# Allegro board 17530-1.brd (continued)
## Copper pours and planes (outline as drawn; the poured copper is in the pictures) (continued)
3D3V_S0 on L3SGND: 181.31,140.4 177.1,144.6 177.1,149.65 175.83,152.19 175.83,152.22 175.81,152.24 175.45,153.58 175.18,155.61 174.69,155.95 172.25,164.31 168.59,167.97 168.59,169.62 167.85,170.37 159.85,170.37 157.36,172.88 157,173.22 156.83,173.52 156.69,174.43 157.26,175 157.26,175.47 156.6,176.13 156.6,179.81 152.54,183.97 152.39,184.13 152.39,184.43 152.4,184.48 152.39,184.5 152.39,184.8 152.4,184.84 152.39,184.88 152.39,185.55 152.51,185.69 152.76,185.69 154.48,185.69 155.42,185.69 156.36,185.69 159.29,182.6 159.2,176.48 159.3,176.21 159.69,175.83 170.1,175.83 174.17,171.77 180.64,171.77 181.17,171.24 181.17,170.5 181.16,170.49 181.17,170.42 181.17,164.89 181.93,164.13 181.93,159.56 183.58,157.91 183.58,146.99 184.33,146.24 192.96,146.24 193.74,145.46 193.74,141.3 192.95,140.4 182.15,140.4 182.12,140.41 182.08,140.4 181.79,140.4 181.78,140.41 181.72,140.4
3D3V_S0 on L3SGND: 111.84,173.04 108.92,175.96 95.93,175.96 95.91,175.93 74.37,175.96 73.36,176.97 70.56,176.97 61.67,185.86 59.01,185.86 58.81,186.06 56.45,188.54 56.45,188.55 56.4,188.6 56.34,188.66 56.34,188.66 56.26,188.66 56.19,188.66 56.19,188.66 36.02,188.66 35.37,189.31 35.37,190.55 37.67,192.85 39.67,192.85 40.82,191.71 58.34,191.71 60.88,189.17 64.07,189.17 65.8,187.93 71.15,184.37 73.31,183.1 73.99,182.69 77.14,182.69 77.41,182.42 77.41,180.01 78.15,179.26 110.16,179.26 113.21,176.21 118.19,176.21 118.7,176.72 119.56,176.72 120.21,176.07 120.21,173.4 120.02,173.04
3D3V_S5 on TOP: 160.4,157.99 155.83,162.56 155.83,164.59 152.91,167.51 152.91,173.23 151,175.13 146.53,175.13 143.79,177.88 115.07,177.88 115.06,177.88 114.55,177.88 114.05,178.38 110.26,178.38 110.08,178.56 103.38,178.56 103.12,178.31 103.12,176.91 103,176.78 101.47,176.78 100.97,177.29 88.77,177.29 88.39,177.67 88.39,180.04 88.77,180.42 114.3,180.42 114.9,179.82 143.9,179.82 147.45,176.28 152.02,176.28 154.18,174.12 154.18,168.02 157.3,164.9 157.3,163.32 159.97,160.66 161.8,160.66 162.18,160.27 162.18,158.24 161.93,157.99
3D3V_S5 on TOP: 184.35,43.48 184.15,43.69 184.15,44.2 185.62,45.67 186.51,45.67 188.09,47.24 188.09,136.78 186.56,138.3 186.56,138.35 186.06,138.86 186.06,145.92 186.94,146.81 188.72,146.81 189.48,146.05 189.48,145.14 187.48,143.13 187.48,139.24 189.56,137.16 189.56,46.51 186.54,43.48
3D3V_S5 on TOP: 29.41,178.13 29.4,178.14 28.77,178.14 28.47,178.44 28.47,189.74 28.63,189.89 29.77,189.89 29.95,189.71 29.95,188.14 30.07,188.01 35.29,188.01 35.49,187.81 35.49,183.32 33.43,181.25 33.43,178.66 32.89,178.13
3D3V_S5 on TOP: 35.94,233.3 35.69,233.55 35.69,235.48 35.86,235.66 36.53,235.66 36.68,235.81 36.68,236.52 36.8,236.65 37.31,236.65 37.34,236.63 37.87,236.63 38.23,236.98 38.23,240.54 37.85,240.92 37.85,243.08 37.62,243.31 36.96,243.31 36.75,243.51 36.75,246.15 36.93,246.33 38.79,246.33 41.53,243.59 41.53,236.22 40.01,234.7 40.01,233.43 39.88,233.3 ; 5 cut-outs
3D3V_S5 on TOP: 176.83,4.19 176.78,4.24 176.78,5.21 176.45,5.54 176.45,6.73 176.5,6.78 177.16,6.78 177.65,7.26 177.65,8.1 178.18,8.64 178.92,8.64 179.04,8.51 179.04,6.73 178.89,6.58 178.05,6.58 177.67,6.2 177.67,4.29 177.57,4.19 ; 1 cut-out
3D3V_S5 on TOP: 11.94,186.82 8.76,189.99 4.32,189.99 1.27,193.04 1.27,232.28 13.53,244.54 17.6,244.54 18.38,245.31 23.8,245.31 24.05,245.06 24.05,242.6 23.65,242.19 14.73,242.19 3.94,231.39 3.94,222.76 4.19,222.5 5.59,222.5 6.17,221.92 6.17,221.17 6.36,220.98 6.36,220.13 6.26,220.03 4.38,220.03 3.39,219.04 3.39,195.23 5.46,193.17 12.29,193.17 15.61,189.85 20.59,189.85 21.08,189.36 21.08,187.07 20.83,186.82 ; 2 cut-outs
3D3V_S5 on BOTTOM: 177.04,32 176.78,32.26 176.78,32.64 176.85,32.7 176.85,33.59 178.05,34.8 178.05,38.63 183.24,43.81 183.64,43.81 184.72,44.89 186.12,44.89 186.46,44.55 186.46,44.37 186.66,44.17 180.05,37.55 180.05,37.1 180.09,37.06 180.09,35.95 179.26,35.13 179.26,33.46 177.8,32
3D3V_S5 on BOTTOM: 50.93,237.87 45.85,242.95 22.17,242.95 21.77,243.36 21.77,245.06 22.07,245.36 47.88,245.36 53.47,239.78 53.47,238 53.34,237.87
3D3V_S5 on L2VCC: 69.55,177.74 59.26,187.9 48.44,187.9 45.26,184.72 37.26,184.72 35.1,182.56 16.73,182.56 16.32,183.07 16.32,188.81 16.14,188.97 16.25,189.44 16.45,189.55 39.45,189.57 41.66,191.76 41.86,191.96 59.36,191.96 69.01,182.31 96.02,182.31 96.29,181.77 95.44,180.93 95.44,178.77 94.41,177.74
3D3V_S5 on L2VCC: 188.01,143.7 187.52,144 187.52,155.78 186.13,157.16 172.51,157.16 171.88,156.53 168.35,156.53 167.72,157.16 159.59,157.16 159.19,157.56 159.19,161.85 159.59,162.24 164.01,162.24 167.18,159.07 187.75,159.07 189.93,156.89 189.93,144.1 189.53,143.7
3D3V_SB on TOP: 151.61,128.12 151.49,128.24 151.49,129.26 151.59,129.36 152.81,129.36 153.42,129.97 153.8,129.97 153.92,129.84 153.92,128.8 153.24,128.12
3D3V_SB on TOP: 171.81,47.7 171.35,48.16 171.35,59.79 171.02,60.12 171.02,66.34 167.97,69.39 167.97,97.59 164.49,101.07 163.12,101.07 160.55,103.63 159.54,103.63 159.28,103.89 159.28,104.65 159.61,104.98 160.81,104.98 163.8,101.98 164.21,101.98 164.24,102.01 165,102.01 169.66,97.35 169.66,70.83 172.67,67.82 172.67,59.98 172.9,59.75 172.9,48.01 172.59,47.7 ; 4 cut-outs
3D3V_SB on TOP: 4.22,211.99 3.68,212.52 3.68,218.16 4.1,218.58 6.21,218.58 6.22,218.57 6.22,216.03 6.99,215.26 8.26,215.26 8.51,215.01 8.51,212.01 8.48,211.99 ; 2 cut-outs
3D3V_SB on TOP: 157.51,144.02 157.25,144.27 157.25,148.11 157.02,148.34 156.46,148.34 156.21,148.59 156.21,149.1 156.46,149.35 157.56,149.35 157.61,149.4 157.61,153.67 158.37,154.43 160.66,154.43 160.67,154.42 160.95,154.42 161.04,154.33 161.04,153.67 160.78,153.42 159.99,153.42 159.99,152.6 159.61,152.22 159.44,152.22 159.33,152.12 159.33,150.42 159.64,150.11 162.23,150.11 162.56,150.44 162.56,150.88 163.42,150.88 163.42,150.7 164.34,150.7 164.64,150.39 164.64,148.89 164.52,148.77 163.75,148.77 163.58,148.95 163.58,149.61 163.45,149.73 162.56,149.73 162.31,149.48 162.31,148.08 162.43,147.96 164.59,147.96 165.1,147.45 165.1,146.69 164.93,146.52 158.99,146.52 158.62,146.15 158.62,144.53 158.12,144.02 ; 23 cut-outs
3D3V_SB on TOP: 156.62,12.62 156.03,13.21 156.03,23.22 155.63,23.62 155.63,24.43 156.01,24.82 156.9,24.82 156.9,24.74 157.23,24.41 157.23,24.33 157.28,24.28 157.28,21.82 157.4,21.69 157.4,14.63 158.27,13.77 159.92,13.77 160.05,13.64 160.05,12.7 159.97,12.62 ; 5 cut-outs
3D3V_SB on TOP: 174.24,46.35 173.99,46.61 173.99,49.91 174.12,50.04 176.28,50.04 176.53,49.78 176.53,46.61 176.28,46.35 ; 1 cut-out
3D3V_SB on TOP: 154.08,139.42 153.95,139.55 153.95,139.93 153.85,140.03 153.31,140.03 153.06,140.28 153.06,141 153.26,141.2 155.35,141.2 155.73,140.82 155.73,140.18 154.97,139.42 ; 1 cut-out
3D3V_SB on TOP: 170.79,34.4 170.5,34.7 168.94,34.7 168.73,34.9 168.73,36.14 169.24,36.65 171.68,36.65 171.86,36.47 171.86,34.7 171.56,34.4
3D3V_SB on TOP: 160.86,155.7 160.78,155.78 160.78,156.34 162.51,158.06 162.51,161.44 162.13,161.82 159.97,161.82 157.96,163.83 157.96,165.51 154.94,168.53 154.94,174.56 154.31,175.2 154.31,177.16 155.07,177.93 160.3,177.93 160.68,177.55 160.68,174.85 160.63,174.8 159.46,174.8 159.31,174.96 159.31,176.28 159.08,176.5 156.57,176.5 156.46,176.4 156.46,174.62 156.59,174.5 156.59,170.31 158.5,168.4 159.51,168.4 159.64,168.28 159.64,166.62 161.42,164.85 162.05,164.85 162.18,164.72 162.18,163.58 162.24,163.51 162.31,163.51 162.31,163.02 162.76,162.56 163.86,162.56 164.67,161.75 165.74,161.75 165.86,161.62 165.86,160.78 165.61,160.53 164.47,160.53 164.08,160.15 164.08,157.1 162.69,155.7 ; 6 cut-outs
3D3V_SB on TOP: 138.38,16.8 138.3,16.88 138.3,18.03 138.3,18.03 138.43,18.16 140.97,18.16 141.1,18.03 141.1,16.93 140.97,16.8 ; 1 cut-out
3D3V_SB on BOTTOM: 154.94,140.08 154.43,140.59 154.43,141.6 155.96,143.13 155.96,146.3 156.34,146.69 156.34,148.34 156.72,148.72 158.37,148.72 158.75,148.34 158.75,143.26 155.57,140.08
3D3V_SB on BOTTOM: 159.56,153.26 159.38,153.44 159.38,154.69 161.67,156.97 162.05,156.97 162.56,156.46 162.56,155.57 160.99,154 160.99,153.72 160.53,153.26
3D3V_SB on BOTTOM: 152.88,128.04 152.02,128.91 152.02,131.44 152.78,132.21 152.78,132.97 151.89,133.86 151.89,139.57 152.53,140.21 152.53,140.59 152.78,140.84 153.67,140.84 154.05,140.46 154.05,132.36 154.46,131.95 154.46,130.48 154.1,130.12 154.1,129.01 154.48,128.63 154.48,128.32 154.2,128.04
3D3V_SB on BOTTOM: outline of 91 points within 6.1,171.81 45.72,239.51
3D3V_SB on BOTTOM: 155.45,23.62 155.19,23.88 155.19,24.77 155.57,25.15 163.19,25.15 165.35,27.3 168.91,27.3 171.83,30.23 171.83,32.51 170.56,33.78 170.56,34.8 170.81,35.05 171.83,35.05 173.35,33.53 173.35,29.46 169.67,25.78 166.37,25.78 164.21,23.62
3D3V_SB on BOTTOM: 148.97,11.56 142.75,17.78 141.48,17.78 141.1,17.4 139.32,17.4 139.19,17.53 139.19,18.8 139.57,19.18 143.51,19.18 149.61,13.08 150.62,13.08 154.94,17.4 154.94,20.07 155.96,21.08 157.1,21.08 157.35,20.83 157.35,19.43 156.46,18.54 156.46,16.64 151.38,11.56
3D3V_SB on L2VCC: 46.21,170.45 45.96,170.69 45.96,171.29 46.31,171.64 49.48,171.64 49.86,172.02 65.23,172.02 66.37,173.16 71.96,173.16 74.37,175.58 96.17,175.55 97.85,177.26 98.36,177.86 98.36,180.39 103.1,185.18 119.56,185.23 120.19,184.59 126.19,184.59 126.7,185.1 150.22,185.1 151.67,184.74 151.69,184.72 151.74,184.72 151.8,184.71 151.82,184.72 160.58,184.72 161.05,184.25 160.72,183.69 160.72,181.16 160.5,180.84 157.16,180.84 157.16,182.2 156.54,182.82 108.76,182.82 104.71,178.77 104.71,174.45 104.44,174.18 78.15,174.18 75.23,171.26 66.98,171.26 66.16,170.45 62.46,170.45 62.41,170.46 62.38,170.45
3D3V_SB on L2VCC: 171.91,46.67 171.51,47.07 171.51,48.82 175.97,53.28 176.74,53.28 178.54,55.13 179.93,55.13 180.72,54.34 184.69,54.34 187.46,57.25 187.52,57.3 187.52,57.3 187.52,57.38 187.52,127.08 186.51,128.08 184.99,128.08 184.34,128.73 184.34,131.49 184.61,131.76 187.25,131.76 189.17,129.84 189.17,50.88 186.61,48.32 181.28,48.32 180.52,47.56 177.47,47.56 176.58,46.67
3D3V_SB on L2VCC: 156.92,114.62 156.65,114.89 156.65,117.68 155.2,119.14 151.25,119.14 150.8,118.68 148.31,118.68 148.15,118.93 148.15,122.45 148.39,122.62 149.78,122.62 149.92,122.48 149.92,122.13 148.91,121.11 148.91,119.8 149.18,119.44 150.04,119.44 150.12,119.52 150.73,120.11 150.83,120.21 156.42,120.21 157.3,121.09 157.66,121.09 157.92,120.83 157.92,115.01 157.53,114.62
3D3V_SB on L3SGND: 30.23,170.45 28.53,172.15 21.8,172.15 15.43,178.51 15.43,179.19 16.32,180.14 16.32,188.67 9.86,195.14 7.06,195.14 5.78,196.42 5.78,196.6 5.9,215.56 6.17,215.84 8.3,215.84 8.7,215.44 8.7,199.31 9.45,198.56 10.72,198.56 18.99,190.29 18.99,178.48 19.48,177.99 21.13,177.99 23.29,175.83 26.59,175.83 27.61,174.82 30.02,174.82 31.67,173.16 48.21,173.16 49.35,172.02 65.23,172.02 66.37,173.16 71.96,173.16 74.37,175.58 96.03,175.55 96.3,175.28 96.3,174.4 96.09,174.18 78.15,174.18 75.23,171.26 66.98,171.26 66.16,170.45
3D3V_SB on L3SGND: 185.12,173.29 184.85,173.56 184.85,179.4 184.36,179.9 168.58,179.9 167.96,179.28 167.96,176.35 167.82,176.21 159.84,176.21 159.58,176.48 159.68,182.75 156.52,186.07 155.42,186.07 154.48,186.07 152.76,186.07 152.34,186.07 152.01,185.7 152.01,184.96 151.7,184.82 151.55,184.97 151.09,185.45 151.08,186.2 151.08,187.23 151.08,187.64 151.44,187.99 154.58,187.99 155.59,188 158.64,186.78 163.5,181.93 185.98,181.93 186.88,181.02 186.88,173.69 186.48,173.29
3D3V_SB on L3SGND: 184.61,128.84 184.34,129.11 184.34,133.56 175.2,142.7 175.2,144.84 174.69,145.6 174.69,149.31 170.76,153.1 166.78,153.1 165.64,154.24 161.34,154.24 160.7,153.61 159.84,153.61 159.58,153.88 159.58,154.35 161.75,156.53 165.66,156.53 166.55,155.64 171.88,155.64 174.36,153.16 174.4,153.11 174.41,153.11 175.48,152.03 176.72,149.56 176.72,144.45 181.69,139.48 181.69,139.46 181.71,139.45 181.72,139.43 181.76,139.41 186.5,134.67 186.5,129.36 185.98,128.84
3D3V_WLAN_SB on TOP: 44.58,208.91 44.32,209.17 41.76,209.17 41.2,209.73 41.2,210.67 41.3,210.77 48.64,210.77 50.04,209.37 50.04,208.91 ; 6 cut-outs
3D3V_WLAN_SB on TOP: 47.88,225.63 47.6,225.91 47.6,226.82 47.04,227.38 41.1,227.38 41.02,227.46 41.02,229.49 40.39,230.12 38.23,230.12 37.47,230.89 37.47,232.79 37.59,232.92 41.27,232.92 41.53,232.66 41.53,231.78 41.67,231.64 50.58,231.64 51.18,231.04 51.18,226.14 50.67,225.63 ; 12 cut-outs
3D3V_WLAN_SB on L2VCC: 47.83,208.98 47.43,209.37 47.43,219 48.96,220.52 48.96,226.39 48.21,227.14 44.91,227.14 44.39,227.66 44.39,229.28 44.73,229.63 44.79,229.68 44.79,229.69 45.04,229.93 51.61,229.93 52.64,228.9 52.64,228.01 52.63,227.98 52.64,227.93 52.64,209.63 51.99,208.98
EDP_AVC12 on TOP: 60.12,18.72 59.59,19.25 57.96,19.25 57.96,19.56 57.99,19.58 59.66,19.58 59.94,19.86 60.83,19.86 61.24,20.27 62.1,20.27 62.18,20.19 62.18,19.74 61.93,19.48 61.37,19.48 60.6,18.72
LAN_CONN_CVT on TOP: 122.1,16.56 121.98,16.68 121.98,18.03 122.12,18.17 123.41,18.17 123.55,18.03 123.55,16.66 123.44,16.56 ; 1 cut-out
PWR_1D0V on TOP: 188.7,146.84 187.91,147.62 187.91,152.63 187.32,153.21 187.32,156.57 187.71,156.95 193.4,156.95 194.44,155.91 194.44,148.59 192.68,146.84 ; 2 cut-outs
PWR_1D0V on BOTTOM: 188.24,146.79 187.83,147.19 187.83,154.76 187.73,154.86 187.73,157.15 187.91,157.33 188.9,157.33 190.4,155.83 193.52,155.83 193.68,155.68 193.68,147.93 192.56,146.81 192.56,146.79
PWR_1D0V_PHASE on TOP: 183.62,160.78 182.98,161.42 182.98,162.53 183.13,162.69 185.29,162.69 185.98,163.37 185.98,167.08 185.55,167.51 185.55,172.59 185.67,172.72 188.47,172.72 188.54,172.64 188.54,167.31 188.81,167.04 190.33,167.04 190.58,166.8 190.58,165.99 190.91,165.66 192.81,165.66 193.68,164.8 193.68,161.67 192.79,160.78 ; 2 cut-outs
PWR_1D0V_PHASE on BOTTOM: 188.59,161.42 186.31,163.7 186.31,170.76 187.86,172.31 188.62,172.31 188.85,172.09 188.85,167.26 189.23,166.88 191.95,166.88 193.29,165.53 193.29,161.8 192.91,161.42
PWR_2D5V on TOP: 113.39,172.34 113.17,172.55 113.17,173.98 113.03,174.12 111.38,174.12 111.28,174.22 111.28,176.2 111.39,176.31 112.83,176.31 113.47,175.67 116.99,175.67 117.6,175.06 117.6,172.42 117.53,172.34 ; 4 cut-outs
PWR_2D5V_VIN on TOP: 108.18,172.11 108.05,172.24 108.05,175.26 107.87,175.44 105.71,175.44 104.98,174.7 103.4,174.7 103.33,174.78 103.33,177.8 103.71,178.18 109.88,178.18 110.9,177.16 110.9,172.19 110.82,172.11
PWR_3D3V on TOP: 22.1,177.29 21.97,177.42 21.97,178.18 22.48,178.69 22.48,181.23 21.84,181.86 21.84,191.11 22.1,191.36 25.7,191.36 26.92,190.14 27.93,190.14 28.16,189.92 28.16,178.18 27.94,177.97 27.94,177.93 27.3,177.29 ; 1 cut-out
PWR_3D3V on BOTTOM: 23.5,178.32 22.62,179.2 22.61,179.2 22.43,179.37 22.43,180.7 21.49,181.64 21.49,190.65 22.35,191.52 26.8,191.52 28.19,190.12 28.19,178.51 28,178.32
PWR_3V_PHASE2 on TOP: 27.48,190.58 27.18,190.88 27.18,191.62 26.77,192.02 18.62,192.02 15.44,195.2 15.44,197.71 16.94,199.21 22.33,199.21 22.86,199.75 22.86,201.04 22.99,201.17 28.83,201.17 28.88,201.12 28.88,198.73 29.08,198.53 32.74,198.53 32.97,198.3 32.97,197.79 32.98,197.78 32.98,192.91 32.83,192.76 28.85,192.76 28.75,192.66 28.75,190.68 28.65,190.58
PWR_3V_PHASE2 on BOTTOM: 18.16,192.66 15.2,195.62 15.2,197.83 15.37,197.99 18.69,197.99 19.08,197.61 32.38,197.61 33.15,196.85 33.15,193.29 32.51,192.66
PWR_5V on TOP: 11.58,222.48 10.54,223.52 10.54,225.81 10.5,225.84 10.5,229.1 11.09,229.68 12.26,229.68 13.56,230.99 33.05,230.99 33.27,230.76 33.27,228.98 32.13,227.84 27.3,227.84 26.92,227.46 26.92,222.61 26.8,222.48 ; 2 cut-outs
PWR_5V on BOTTOM: 11.58,222.83 10.41,224 10.41,224.28 10.43,224.29 10.43,226.71 12.06,228.35 12.06,230.2 12.38,230.52 25.9,230.52 26.42,231.04 32.38,231.04 32.4,231.03 33.13,231.03 33.27,230.89 33.27,228.8 32.23,227.76 32.23,227.71 32.18,227.66 31.47,227.66 29.46,225.65 26.64,225.65 26.09,225.09 22.48,225.09 21.49,224.1 15.47,224.1 14.2,222.83
PWR_5V3D3V_VIN on TOP: 43.81,198.25 42.53,199.53 36.58,199.53 34.81,201.29 34.8,201.29 34.67,201.42 22.86,201.42 22.49,201.79 22.49,213.5 22.77,213.78 29.97,213.78 30.23,213.53 30.23,207.77 30.76,207.24 41.4,207.24 41.41,207.23 42.37,207.24 46.28,205.28 46.55,205.02 46.55,198.44 46.35,198.25
PWR_5V3D3V_VIN on BOTTOM: 38.71,200.28 38.71,204.55 39.01,204.85 46.41,204.85 46.43,204.83 46.43,199.85 46.42,199.83 46.42,199.07 46.1,198.75 40.23,198.75
PWR_5V3D3V_VIN on L2VCC: 23.95,199.71 22.42,201.25 22.42,213.15 23.07,213.8 29.77,213.8 30.16,213.41 30.16,208.33 31.16,207.33 43.26,207.33 46.29,205.75 46.29,200.1 45.9,199.71
PWR_5V_PHASE1 on TOP: 20.32,209.55 19.81,210.06 18.41,210.06 17.78,210.69 17.78,211.96 17.4,212.34 15.37,212.34 14.61,213.11 14.61,220.5 16.18,222.07 27.71,222.07 27.79,222 27.79,216.51 27.56,216.28 24.26,216.28 23.62,215.65 23.62,214.12 23.5,214 22.73,214 22.23,213.49 22.23,209.68 22.1,209.55
PWR_5V_PHASE1 on BOTTOM: 18.03,209.55 17.53,210.06 17.53,211.71 17.14,212.09 15.62,212.09 15,212.71 15,220.71 16.41,222.12 27.56,222.12 27.81,221.87 27.81,217.47 27.28,216.94 22.63,216.94 21.72,216.03 21.72,210.06 21.21,209.55
PWR_12V_DUAL_1D0V on TOP: 189,167.36 188.85,167.51 188.85,173.13 188.37,173.61 187.53,173.61 187.29,173.85 187.29,175.4 187.4,175.51 191.77,175.51 192.02,175.77 192.02,177.04 192.15,177.16 192.79,177.16 192.91,177.04 192.91,176.28 193.29,175.9 193.29,174.24 193.42,174.12 193.42,168.4 193.17,168.15 191.77,168.15 191.64,168.28 191.64,168.76 191.57,168.83 189.89,168.83 189.84,168.78 189.84,167.44 189.76,167.36
PWR_DDR4_LDOIN on TOP: 40.34,181.46 39.52,182.27 39.52,186.08 39.75,186.31 41.02,186.31 41.27,186.06 41.27,181.66 41.07,181.46
PWR_DDR4_LX on TOP: 54.84,173.51 54.7,173.65 54.7,179.13 55.04,179.48 58.04,179.48 58.24,179.68 58.24,181.89 57.56,182.58 57.56,185.9 57.81,186.16 60.83,186.16 60.96,186.03 60.96,184.15 61.47,183.64 63.25,183.64 66.93,179.96 66.93,177.29 66.17,176.54 63.82,176.54 60.79,173.51 ; 1 cut-out
PWR_DDR4_LX on BOTTOM: 55.37,173.99 54.99,174.37 54.99,179.32 55.12,179.45 57.91,179.45 58.17,179.71 58.17,181.36 58.67,181.86 64.64,181.86 67.18,179.32 67.18,177.16 66.67,176.66 63.5,176.66 62.23,175.39 60.96,175.39 59.56,173.99
PWR_GT_SW1 on TOP: 18.01,77.22 17.7,77.52 17.7,80.72 17.4,81.03 15.42,81.03 14.94,81.51 14.94,82.37 14.76,82.55 13.18,82.55 12.78,82.96 12.78,87.07 12.85,87.15 14.61,87.15 14.86,87.4 14.86,90.37 14.73,90.5 13.87,90.5 13.77,90.6 13.77,91.16 14.05,91.44 19.81,91.44 20.32,90.93 20.32,84.84 21.34,83.82 23.5,83.82 23.75,83.57 23.75,77.34 23.62,77.22 ; 1 cut-out
PWR_GT_SW1 on BOTTOM: 15.37,83.95 14.86,84.45 14.86,91.19 15.11,91.44 19.18,91.44 19.68,90.93 19.68,84.33 19.3,83.95
PWR_GT_SW1 on L2VCC: 17.81,77.25 17.67,77.4 17.67,80.62 17.25,81.04 15.4,81.04 15.02,81.41 15.02,82.43 14.58,82.87 12.93,82.87 12.76,83.02 12.76,86.86 12.94,87 12.95,87.01 14.43,87.01 14.9,87.47 14.9,90.15 14.58,90.46 14.02,90.46 13.88,90.6 13.88,91.16 14.18,91.45 19.94,91.45 20.31,91.08 20.31,84.87 20.46,84.68 21.38,83.76 23.44,83.76 23.71,83.49 23.71,77.45 23.52,77.25
PWR_GT_SW2 on TOP: 13.97,95.12 12.7,96.39 12.7,105.03 12.95,105.28 14.71,105.28 15.06,105.64 15.06,107.49 14.9,107.66 14.26,107.66 14.03,107.89 14.03,108.39 14.22,108.58 21.03,108.58 21.41,108.2 21.41,106.27 21.79,105.89 23.57,105.89 24.05,105.41 24.05,104.29 23.77,104.01 21.74,104.01 21.46,103.73 21.46,96.77 19.81,95.12
PWR_GT_SW2 on BOTTOM: 16,95.38 15.24,96.14 15.24,108.33 15.62,108.71 21.08,108.71 21.59,108.2 21.59,97.92 20.45,96.77 20.45,95.63 20.19,95.38
PWR_GT_SW2 on L2VCC: 14.15,94.96 13.29,95.82 13.29,95.83 13.23,95.87 12.76,96.34 12.76,104.95 13.06,105.24 14.46,105.24 14.9,105.69 14.9,106.94 14.11,107.72 14.11,108.38 14.26,108.55 21.23,108.55 21.45,108.33 21.45,106.27 22.02,105.7 23.87,105.7 24.07,105.51 24.07,104.19 23.87,104 21.84,104 21.37,103.53 21.37,96.52 19.81,94.96
PWR_RT6575_VIN on TOP: 15.24,199.57 15.09,199.72 15.09,202.39 14.66,202.82 14.66,203.05 14.83,203.23 15.14,203.23 15.67,202.69 17.2,202.69 17.3,202.59 17.3,201.47 17.14,201.32 16.74,201.32 16.51,201.09 16.51,199.75 16.33,199.57 ; 1 cut-out
PWR_V_12V_CPU_S0_VSA on TOP: 124.26,36.45 124.08,36.63 124.08,41.78 124.79,42.49 124.79,44.04 124.64,44.2 123.27,44.2 123.09,44.37 123.09,45.06 123.22,45.19 128.45,45.19 128.65,44.98 128.65,43.36 127.2,41.91 127.2,36.91 126.75,36.45 ; 2 cut-outs
PWR_VCCIO_VIN on TOP: 118.2,85.64 118.06,85.78 118.06,90.83 119.43,92.2 125.6,92.2 125.98,91.82 125.98,86.74 125.73,86.49 125.09,86.49 124.24,85.64 ; 2 cut-outs
PWR_VCCSA_PHASE on TOP: 120.65,41.71 120.6,41.76 120.6,42.52 120.36,42.76 119.29,42.76 118.49,43.56 118.49,52.07 118.62,52.2 119.76,52.2 119.89,52.07 119.89,50.42 120.4,49.91 122.48,49.91 122.66,49.73 122.66,48.72 122.91,48.46 128.5,48.46 128.6,48.36 128.6,45.67 128.45,45.52 122.86,45.52 122.4,45.06 122.4,42.55 121.56,41.71 ; 2 cut-outs
PWR_VCCSA_PHASE on BOTTOM: 119,43.18 118.49,43.69 118.49,49.45 118.95,49.91 122.25,49.91 123.98,48.18 127.1,48.18 127.38,47.9 127.38,45.09 125.48,43.18
PWR_VCORE_SW1 on TOP: 37.52,36.17 37.36,36.32 37.36,37.31 36.96,37.72 32.79,37.72 32.69,37.82 32.69,51.87 33.15,52.32 34.92,52.32 35.31,51.94 35.31,50.42 35.56,50.16 37.85,50.16 38,50.01 38,45.77 38.85,44.92 44.87,44.92 46.27,43.52 46.27,36.87 46.1,36.7 42.93,36.7 42.8,36.83 42.8,38.73 42.61,38.93 39.8,38.93 39.37,38.49 39.37,37.82 39.24,37.69 38.53,37.69 38.46,37.62 38.46,36.32 38.3,36.17 ; 1 cut-out
PWR_VCORE_SW1 on BOTTOM: 33.05,38.46 32.79,38.71 32.79,49.43 33.15,49.78 37.74,49.78 38,49.53 38,45.44 38.63,44.81 45.36,44.81 46.13,44.04 46.13,40.87 44.48,39.22 42.7,39.22 42.32,39.6 39.52,39.6 39.4,39.47 39.4,38.58 39.27,38.46
PWR_VCORE_SW1 on L2VCC: 42.88,36.89 42.74,37.04 42.74,38.56 42.37,38.93 39.8,38.93 39.31,38.43 39.31,37.67 39.16,37.53 33.1,37.53 32.7,37.92 32.7,51.74 32.97,52.01 34.7,52.01 34.99,51.63 34.99,50.59 35.48,50.1 37.79,50.1 38.04,49.94 38.04,45.64 38.78,44.89 46.15,44.89 46.55,44.5 46.55,36.89
PWR_VCORE_SW2 on TOP: 55.5,40.36 55.37,40.49 55.37,41.63 55.14,41.86 51.23,41.86 51.1,41.99 51.1,54.2 51.51,54.61 52.7,54.61 52.96,54.86 52.96,56.26 53.34,56.64 54.99,56.64 56.39,55.24 56.39,48.26 56.67,47.98 57.56,47.98 58.45,48.87 64.03,48.87 65.05,47.85 65.05,41.63 64.82,41.4 61.24,41.4 61.24,43.15 60.6,43.79 57.94,43.79 57.81,43.66 57.81,42.77 57.68,42.65 56.87,42.65 56.57,42.34 56.57,40.59 56.34,40.36 ; 2 cut-outs
PWR_VCORE_SW2 on BOTTOM: 51.38,42.8 51.21,42.98 51.21,51.16 51.33,51.28 52.35,51.28 56.54,47.09 61.04,47.09 61.77,47.83 64.34,47.83 64.67,47.5 64.67,43.41 64.06,42.8
PWR_VCORE_SW2 on L2VCC: 55.45,40.45 55.31,40.59 55.31,41.48 54.94,41.85 51.28,41.85 51.12,42.09 51.12,54.15 51.39,54.42 52.68,54.42 53.02,54.93 53.02,56.31 53.29,56.58 55.17,56.58 56.58,55.17 56.58,49.58 57.33,48.83 64.18,48.83 64.83,48.18 64.83,42.08 64.62,41.62 61.52,41.62 61.15,41.99 61.15,43.26 60.66,43.75 58.09,43.75 57.72,43.39 57.72,42.62 57.58,42.48 57.07,42.48 56.71,42.12 56.71,40.59 56.56,40.45
PWR_VCORE_SW3 on TOP: 79.78,45.11 79.78,46.84 79.27,47.35 76.48,47.35 76.35,47.22 76.35,46.33 76.23,46.2 75.21,46.2 75.08,46.08 75.08,45.49 74.98,45.39 74.24,45.39 74.19,45.44 74.19,46.71 73.96,46.94 69.39,46.94 69.39,58.95 69.47,59.03 71.07,59.03 71.37,59.33 71.37,61.19 71.55,61.37 72.64,61.37 74.68,59.33 74.68,53.59 74.83,53.44 80.92,53.44 83.08,51.28 83.08,45.11 ; 1 cut-out
PWR_VCORE_SW3 on BOTTOM: 79.91,45.06 79.78,45.19 79.78,46.84 79.27,47.35 76.48,47.35 76.35,47.22 76.35,46.33 76.23,46.2 74.7,46.2 73.94,46.96 70,46.96 69.62,47.35 69.62,55.35 69.88,55.6 71.15,55.6 72.42,54.33 72.75,54.33 75.44,51.64 79.86,51.64 80.04,51.46 80.82,51.46 80.92,51.56 80.92,52.1 81.2,52.37 82.63,52.37 83.08,51.92 83.08,45.19 82.96,45.06
PWR_VCORE_SW3 on L2VCC: 74.25,45.4 74.1,45.54 74.1,46.56 73.74,46.93 69.67,46.93 69.41,47.2 69.41,58.85 69.67,59.12 70.82,59.12 71.31,59.61 71.31,61.14 71.58,61.4 72.57,61.4 74.61,59.36 74.61,53.9 75.11,53.4 80.95,53.4 83.12,51.23 83.12,45.8 82.73,45.4 79.96,45.4 79.69,45.67 79.69,46.81 79.33,47.18 76.66,47.18 76.26,46.98 76.26,46.18 76.12,46.04 75.61,46.04 74.98,45.4
PWR_VCORE_SW4 on TOP: 92.68,44.58 92.53,44.73 92.53,45.9 92.25,46.18 87.93,46.18 87.93,60.12 88.39,60.58 89.53,60.58 91.9,58.22 93.22,58.22 93.22,54.86 95.4,52.68 101.37,52.68 101.5,52.55 101.5,45.06 101.42,44.98 98.07,44.98 98.07,46.96 97.82,47.22 94.77,47.22 94.61,47.07 94.61,46.1 94.49,45.97 93.83,45.97 93.6,45.75 93.6,44.68 93.5,44.58 ; 1 cut-out
PWR_VCORE_SW4 on BOTTOM: 88.29,46.08 88.16,46.2 88.16,57 88.42,57.25 90.45,57.25 95.53,52.17 98.32,52.17 98.45,52.3 100.13,52.3 100.63,51.79 100.63,47.27 99.44,46.08
PWR_VCORE_SW4 on L2VCC: 92.66,44.64 92.52,44.78 92.52,45.67 92.15,46.04 88.09,46.04 87.95,46.18 87.95,60.33 88.31,60.52 89.58,60.52 91.87,58.23 93.14,58.23 93.28,58.09 93.28,54.91 95.43,52.77 101.01,52.77 101.41,52.37 101.41,45.16 101.27,45.02 98.27,45.02 97.98,45.4 97.98,46.81 97.61,47.18 94.92,47.18 94.55,46.81 94.55,46.05 94.41,45.91 93.77,45.91 93.54,45.67 93.54,44.75 93.48,44.64
PWR_VDDQ on TOP: 65.15,172.64 64.92,172.87 64.92,175.49 65.2,175.77 67.72,175.77 68.12,176.17 68.12,181.86 68.63,182.37 77.14,182.37 77.24,182.27 77.24,182.12 77.09,181.97 77.09,180.06 77.44,179.71 77.44,178.84 78.41,177.88 78.41,172.77 78,172.77 76.73,174.04 66.24,174.04 66.19,173.99 66.19,172.8 66.04,172.64 ; 2 cut-outs
PWR_VDDQ_VIN on TOP: 50.09,179.15 49.86,179.37 49.86,190.32 50.29,190.75 56.77,190.75 57.43,190.09 57.43,182.12 57.3,181.99 52.22,181.99 51.66,181.43 51.66,179.22 51.59,179.15 ; 1 cut-out
PWR_VTT on TOP: 36.75,176.53 36.7,176.58 36.7,181.94 36.91,182.14 39.19,182.14 40.31,181.03 40.31,180.39 40.26,180.34 39.27,180.34 39.14,180.21 39.14,179.73 39.01,179.6 38.28,179.6 37.92,179.25 37.92,177.04 37.44,176.56 37.44,176.53
TPM_VDD_P8 on TOP: 158.62,168.78 158.12,169.29 158.12,172.21 158.37,172.47 159.28,172.47 159.41,172.34 159.41,171.7 159.52,171.59 161.02,171.59 161.16,171.45 161.16,170.94 160.91,170.69 160.76,170.69 160.76,168.91 160.63,168.78 ; 5 cut-outs
U1.1 on TOP: 37.52,257.25 37.52,256.49 37.39,256.36 33.66,256.36 33.63,256.39 33.63,256.82 33.78,256.97 34.39,256.97 34.77,257.35 37.41,257.35
U1.1 on TOP: 37.39,256.36 33.66,256.36 33.63,256.39 33.63,256.82 33.78,256.97 34.39,256.97 34.77,257.35 37.41,257.35 37.52,257.25 37.52,256.49
U1.1 on TOP: 33.66,256.36 33.63,256.39 33.63,256.82 33.78,256.97 34.39,256.97 34.77,257.35 37.41,257.35 37.52,257.25 37.52,256.49 37.39,256.36
U1.1 on TOP: 37.52,256.49 37.39,256.36 33.66,256.36 33.63,256.39 33.63,256.82 33.78,256.97 34.39,256.97 34.77,257.35 37.41,257.35 37.52,257.25
V_3_CARD_BD on TOP: 41.4,263.4 41.27,263.52 41.27,268.1 41.66,268.48 42.93,268.48 43.05,268.35 43.05,263.73 42.72,263.4 ; 4 cut-outs
V_CPU_ST_PLL on TOP: 89.79,94.54 89.26,95.07 89.26,95.35 89.38,95.48 89.59,95.48 89.69,95.38 90.06,95.38 90.27,95.58 90.52,95.58 90.65,95.46 91.03,95.46 91.16,95.58 91.16,95.84 91.28,95.96 91.92,95.96 92.05,95.84 92.05,94.82 91.92,94.69 90.27,94.69 90.12,94.54

Small or netless copper shapes (teardrops, artwork), in the pictures only: 4 on TOP, 4 on BOTTOM

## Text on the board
Ref Des/Silkscreen Top: 1-2 SHORT : ME DISABLE | 1-2 OPEN : DEFAULT | 3-4 SHORT : DEFAULT | 3-4 OPEN : PASSWORD RESET | 5-6 SHORT : RTC_CMOS RESET | 5-6 OPEN : DEFAULT | Card_Reader | OPERATION | FUNCTION | JUMPER | Service Mode | JMP1 | PW   CLR | CMOS   CLR | 3 | 1 | 5 | 2 | 4 | 6 | F3301:1.5A/6V | F5901:1.1A/6V | X1801:24MHZ | NIC_USB | X1802:32.768KHZ | X3101:25MHZ | AUDIO2 | HDMI | AUDIO1 | USB2.0 | SSUSB_F | GE0721 | 17530-1 | P9Y5R | MADE IN TAIWAN
User.29: ATX_CPU | RTC
User.31: ByImpedance:100.0_DP@_REF_L1=("4.0/12.0(L2)" "3.5/9.0(L2)")|Type="DP"|_REF_L4=("4.0/12.0(L3)" "3.5/9.0(L3)")|imp="100.0" | ByImpedance:32.0_SE@_REF_L1=("9.5(L2)")|Type="SE"|_REF_L4=("9.5(L3)")|_REF_L3=("9.0(L2/L4)")|imp="32.0" | ByImpedance:34.0_SE@_REF_L1=("9.0(L2)")|Type="SE"|_REF_L4=("9.0(L3)")|_REF_L3=("8.0(L2/L4)")|imp="34.0" | ByImpedance:35.0_SE@_REF_L1=("8.5(L2)")|Type="SE"|_REF_L4=("8.5(L3)")|_REF_L3=("7.5(L2/L4)")|imp="35.0" | ByImpedance:37.5_SE@_REF_L1=("7.5(L2)")|Type="SE"|_REF_L4=("7.5(L3)")|_REF_L3=("7.0(L2/L4)")|imp="37.5" | ByImpedance:39.0_SE@_REF_L1=("7.0(L2)")|Type="SE"|_REF_L4=("7.0(L3)")|_REF_L3=("6.5(L2/L4)")|imp="39.0" | ByImpedance:40.0_SE@_REF_L1=("6.5(L2)")|Type="SE"|_REF_L4=("6.5(L3)")|_REF_L3=("6.0(L2/L4)")|imp="40.0" | ByImpedance:42.0_SE@_REF_L1=("6.0(L2)")|Type="SE"|_REF_L4=("6.0(L3)")|_REF_L3=("5.5(L2/L4)")|imp="42.0" | ByImpedance:45.0_SE@_REF_L1=("5.0(L2)")|Type="SE"|_REF_L4=("5.0(L3)")|_REF_L3=("4.5(L2/L4)")|imp="45.0" | ByImpedance:50.0_SE@_REF_L1=("4.0(L2)")|Type="SE"|_REF_L4=("4.0(L3)")|_REF_L3=("4.0(L2/L4)")|imp="50.0" | ByImpedance:60.0_DP@_REF_L1=("9.0/5.0(L2)")|Type="DP"|_REF_L4=("9.0/5.0(L3)")|_REF_L3=("8.0/5.0(L2/L4)")|imp="60.0" | ByImpedance:62.0_DP@_REF_L1=("8.5/5.0(L2)")|Type="DP"|_REF_L4=("8.5/5.0(L3)")|_REF_L3=("7.5/5.0(L2/L4)")|imp="62.0" | ByImpedance:65.0_DP@_REF_L1=("8.0/5.0(L2)")|Type="DP"|_REF_L4=("8.0/5.0(L3)")|_REF_L3=("7.0/5.5(L2/L4)")|imp="65.0" | ByImpedance:68.0_DP@_REF_L1=("6.5/4.0(L2)" "7.5/6.0(L2)")|Type="DP"|_REF_L4=("6.5/4.0(L3)" "7.5/6.0(L3)")|_REF_L3=("6.5/6.0(L2/L4)")|imp="68.0" | ByImpedance:70.0_DP@_REF_L1=("7.0/5.0(L2)")|Type="DP"|_REF_L4=("7.0/5.0(L3)")|_REF_L3=("6.0/5.0(L2/L4)")|imp="70.0" | ByImpedance:72.0_DP@_REF_L1=("7.0/7.0(L2)")|Type="DP"|_REF_L4=("7.0/7.0(L3)")|_REF_L3=("5.5/5.0(L2/L4)")|imp="72.0" | ByImpedance:80.0_DP@_REF_L1=("6.0/9.0(L2)" "4.5/4.0(L2)" "5.0/5.0(L2)")|Type="DP"|_REF_L4=("5.0/5.0(L3)" "6.0/9.0(L3)" "4.5/4.0(L3)")|_REF_L3=("4.5/6.0(L2/L4)")|imp="80.0" | ByImpedance:85.0_DP@_REF_L1=("5.0/7.0(L2)" "4.0/4.5(L2)")|Type="DP"|_REF_L4=("5.0/7.0(L3)" "4.0/4.5(L3)")|_REF_L3=("4.0/6.0(L2/L4)")|imp="85.0" | ByImpedance:90.0_DP@_REF_L1=("4.0/6.0(L2)")|Type="DP"|_REF_L4=("4.0/6.0(L3)")|_REF_L3=("4.0/9.0(L2/L4)")|imp="90.0" | ByImpedance:95.0_DP@_REF_L1=("4.0/8.0(L2)" "3.5/6.0(L2)")|Type="DP"|_REF_L4=("3.5/6.0(L3)" "4.0/8.0(L3)")|imp="95.0" | LayerIndex:nil | Source:4-1.6-8i.xls | artWorks:("_REF_L4" "_REF_L1" "_REF_L3") | gtImpOutlineUsed:BOARD GEOMETRY/PANEL_OUTLINE
User.32: Board Accuracy Check,Feb 02 09:23:29 2018,Passed | Dummy-Static-No Shape On Layer Check,Feb 02 09:23:29 2018,Passed | Solder Bump Check,Nov 08 08:06:12 2017,150 errors | Split Plane Check,Dec 15 10:31:05 2017,Passed
User.45: Note:Refer to DRILL layer for ELLIPSE drill direction | FIGURE | SIZE | 10.0 | 12.0 | 16.0 | 20.0 | 25.0 | 26.0 | 28.0 | 29.0 | 30.0 | 35.0 | 36.0 | 37.0 | 39.0 | 40.0 | 41.0 | 52.0 | 54.0 | 56.0 | 64.0 | 91.0 | 109.0 | 126.0 | 46.0 | 48.0 | 50.0 | 60.0 | 65.0 | 67.0 | 86.0 | 93.0 | 97.0 | 119.0 | 150.0 | 158.0 | 190.0 | 56.0x24.0 | 63.0x36.0 | 91.0x32.0 | 95.0x36.0 | 97.0x48.0 | DRILL CHART: TOP to BOTTOM | ALL UNITS ARE IN MILS | PLATED | NON-PLATED | QTY | 1346 | 2123 | 1126 | 48 | 14 | 576 | 182 | 36 | 7 | 16 | 50 | 29 | 21 | 6 | 10 | 12 | 1 | 2 | 4 | 3 | 11 | 8 | This gerber is just for your reference to find the DP impedance traces in layer L1. | This gerber is just for your reference to find the DP impedance traces in layer L3. | This gerber is just for your reference to find the DP impedance traces in layer L4. | This gerber is just for your reference to find the SE impedance traces in layer L1. | This gerber is just for your reference to find the SE impedance traces in layer L3. | This gerber is just for your reference to find the SE impedance traces in layer L4. | DP IMPEDANCE TABLE: L1 | DP IMPEDANCE TABLE: L3 | DP IMPEDANCE TABLE: L4 | SE IMPEDANCE TABLE: L1 | SE IMPEDANCE TABLE: L3 | SE IMPEDANCE TABLE: L4 | * - Denotes that this Impedance | is NOT used | Model | Eagle SFF | Eagle SFF - ECO: 939788; | PCB_NO | 17530 | VER. | Layer | DRILL | L1 | L2VCC | TMASK | TPLACE | TSILK | TSMD | Designer | EVAR LIU | Gambit MLK SFF - ECO: 939798 | Date | 02/02/2018 | IMP(Ohm) | *32.0 | *60.0 | *34.0 | *62.0 | 62.0 | *35.0 | *65.0 | *37.5 | *68.0 | 68.0 | *39.0 | 70.0 | *40.0 | *70.0 | *72.0 | *42.0 | *80.0 | *45.0 | *85.0 | *90.0 | 85.0 | *95.0 | *100.0 | 100.0 | WIDTH(mils) | 9.0 | 9.5 | 8.0 | 7.5 | 8.5 | 7.0 | 6.5 | 6.0 | 5.5 | 4.5 | 5.0 | 4.0 | 9.0/5.0 | 8.5/5.0 | 8.0/5.0 | 6.5/4.0 | 7.5/6.0 | 7.0/5.0 | 7.0/7.0 | 5.0/5.0 | 6.0/9.0 | 4.5/4.0 | 5.0/7.0 | 4.0/4.5 | 4.0/6.0 | 3.5/6.0 | 4.0/8.0 | 4.0/12.0 | 3.5/9.0 | 7.5/5.0 | 7.0/5.5 | 6.5/6.0 | 6.0/5.0 | 5.5/5.0 | 4.5/6.0 | 4.0/9.0 | TYPE | SE | DP | Ref. Plane | L2 | L2/L4 | L3 | BMASK | BPLACE | BSILK | BSMD | L3SGND | L4
